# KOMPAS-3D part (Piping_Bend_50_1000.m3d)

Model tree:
1. Plane XY
2. Plane ZX
3. Plane ZY
4. X Axis
5. Y Axis
6. Z Axis
7. Origin
8. Sketch:1
9. Sketch:5
10. Sweep:1
     Толщина стенки 1 = 1
11. Control point:1
12. Attachment Point:1
13. Attachment Point:2

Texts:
  Bend-90 Dn 50
  Steel ASTM A295
  Three Point Plane
  Plane at Angle
  Line and Point Plane
  Axis through Two Vertices
  Axis of Feature
  Axis of Conical Surface
  Axis through Edge
  Приклеить элемент выдавливания
  Приклеить элемент вращения
  Приклеить кинематический элемент
  Приклеить элемент по сечениям
  Trim by Surface
  Trim by Sketch
  Feature with No History
  Intersection Axis of Two Planes
  Two Line Plane
  Line and Face Plane
  Bend by line
  Hole in sheet body
  Cut in sheet body
  Point in CM
  Linear Dimension from Line to Point
  Surface Finish Symbol
  Geometric Tolerance Symbol
  Текст на чертеже
  Линия-выноска #1
  Линия-выноска #2
  Линия-выноска #3
  Отклонения формы и база
  Марка координационной оси
  Марка/позиционное обозначение с линией-выноской
  Марка/позиционное обозначение на линии
  Марка/позиционное обозначение без линии-выноски
  Марки/позиционные обозначения с линией-выноской
  Марки/позиционные обозначения на линии
  Марки/позиционные обозначения без линии-выноски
